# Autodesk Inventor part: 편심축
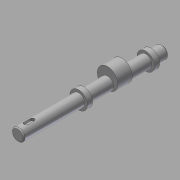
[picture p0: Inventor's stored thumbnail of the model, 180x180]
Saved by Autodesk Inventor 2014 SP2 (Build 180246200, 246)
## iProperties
Created: 2016-02
Part Number: 편심축
Material: 강철, 연강
Document SubType Name: Modeling
Designer: mduedu
Density: 1 g/cm^3
Appearance: 강철
Author: mduedu
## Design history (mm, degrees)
sketch "스케치1"
  geometry: C1 r 6 at (0, 0); 1 further point
  constraints: 1 centre point, 1 coincident
  dimensions: "d0" = 12 diameter of C1
extrude "돌출1" new body sketch "스케치1" distance "d1" = 140; taper "d2" = 0 deg
chamfer "모따기1" distance "d3" = 1; stored, may be unused: second distance "d4" = 2, angle "d5" = 45 deg
node "작업 평면1"
sketch "스케치2"
  geometry: C1 r 10 at (0, 4); C2 r 6 at (0, 0) reference; 1 further point
  constraints: 1 centre point, 1 tangent, 1 vertical alignment
  dimensions: "d7" = 20 diameter of C1
extrude "돌출2" join sketch "스케치2" stored distance "d8" = 14; taper "d9" = 0 deg
node "작업 평면2"
sketch "스케치3"
  geometry: C1 r 8.5 at (0, 0); 1 further point
  constraints: 1 centre point, 1 coincident
  dimensions: "d12" = 17 diameter of C1
extrude "돌출3" join sketch "스케치3" distance "d13" = 5; taper "d14" = 0 deg
node "작업 평면3"
sketch "스케치4"
  geometry: L1 (-5, 140)-(5, 140) reference; L2 (0, 140)-(0, 0); L3 (-2, 132)-(-2, 126); L4 (2, 126)-(2, 132); A1 r 2 centre (0, 132) between (2, 132) and (-2, 132); A2 r 2 centre (0, 126) between (-2, 126) and (2, 126)
  constraints: 6 end point, 4 point on circle, 4 tangent, 2 centre point, 2 point on line, 1 midpoint, 1 parallel, 1 perpendicular
  dimensions: "d15" = 4 distance between parallel lines of L3 L4; "d17" = 6 distance edge to line of A1 L1; "d18" = 10 dimension on A2 A1
extrude "돌출4" cut sketch "스케치4" distance "d19" = 2.5; taper "d20" = 0 deg
sketch "스케치5"
  geometry: L1 (6, 53)-(6, 139) reference; L2 (-6, 53)-(-6, 139) reference; L3 (6, 115)-(-6, 115); L4 (-5, 140)-(5, 140) reference; L5 (6, 116.5)-(4.5, 115); L6 (6, 116.5)-(6, 115); L7 (4.5, 115)-(6, 115); 1 further point
  constraints: 8 end point, 4 point on line, 2 collinear, 1 perpendicular
  dimensions: "d21" = 25 distance between parallel lines of L3 L4; "d22" = 3 diameter of L5.start L3; "d24" = 45 deg angle of L3 L5
revolve "회전1" sketch "스케치5" stored, may be unused: angle "d25" = 90 deg
sketch "스케치6"
  geometry: L1 (6, 116.5)-(4.5, 115) reference; L2 (6, 113.5)-(4.5, 115) reference; 2 further points
  constraints: 1 coincident
node "작업 평면4"
sketch "스케치7"
  geometry: C1 r 8.5 at (0, -4); 1 further point
  constraints: 1 centre point, 1 coincident
  dimensions: "d27" = 17 diameter of C1
extrude "돌출5" join sketch "스케치7" distance "d29" = 5; taper "d30" = 0 deg
node "솔리드1"
other parameters: "d6" = -46, "d11" = -11, "d26" = 28
